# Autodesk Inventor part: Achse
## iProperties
Created: 2003-04
Part Number: Achse
Material: Stahl
Document SubType Name: Modellieren
Designer: Administrator
Control State: 0
Master: False
Checked Out: False
Shininess: 20.0
Angle Display Precision: 2
Document Length Units: 11269
Document Angle Units: 11279
Document Time Units: 11290
Document Mass Units: 11283
Document Length Units Precision: 3
Document Angle Units Precision: 2
Density: 0.0
Volumn: 0.0
Area: 0.0
PropertySet Name: Model Information
Author: Administrator
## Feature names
1. Drehung1 [Revolution]
2. Fase1 [Chamfer]
